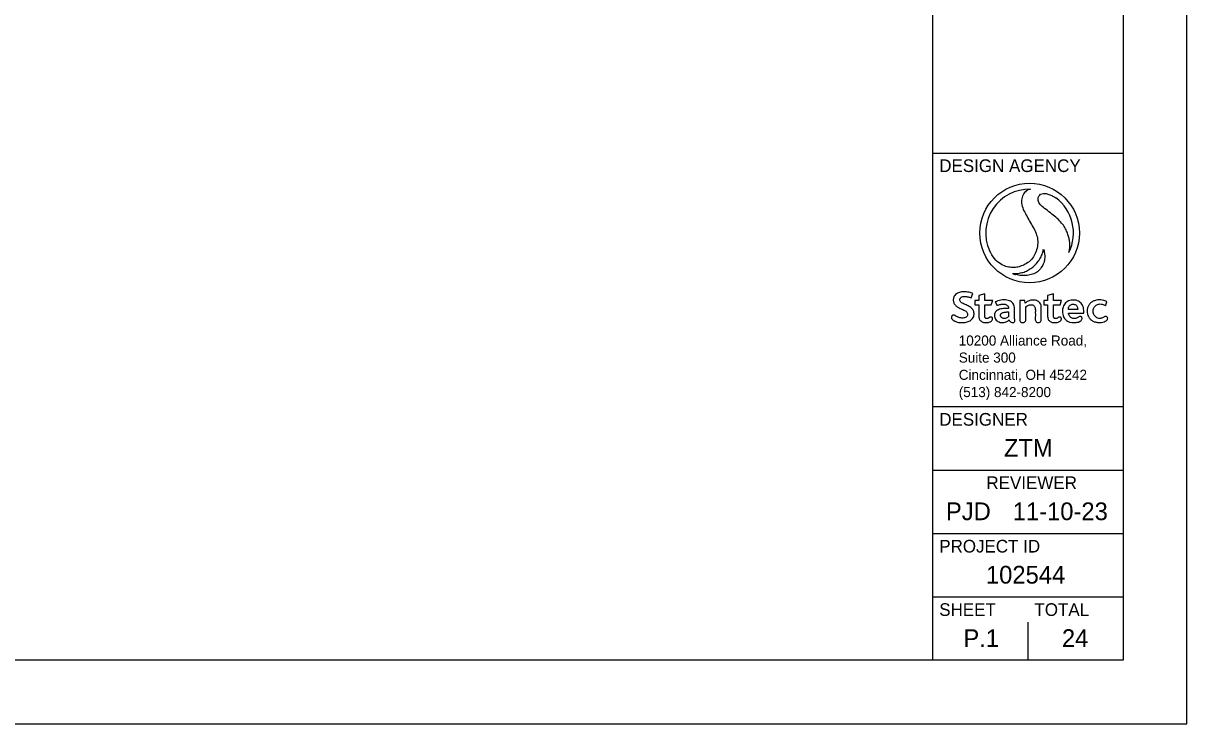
# Model space of a CAD drawing. Extents: x 0 to 45, y -99 to 22.
# Drawn here: x 24.83 to 34, y 0 to 5.52 of the extents above; entities that cross this region are included whole.
import ezdxf

# ---------------------------------------------------------------- set-up
doc = ezdxf.new("R2010")
doc.units = 0
for name, color, linetype in [('SH_Border', 7, 'Continuous'), ('SH_Cut_Line', 7, 'Continuous'), ('SH_Data', 7, 'Continuous'), ('SH_Text', 7, 'Continuous')]:
    doc.layers.add(name, color=color, linetype=linetype)

msp = doc.modelspace()

# ---------------------------------------------------------------- linework, layer by layer
at = {"layer": 'SH_Border'}
for p, q in [((32, 0.5), (32, 21.5)), ((32, 4.5), (33.5, 4.5)), ((32, 2.5), (33.5, 2.5)), ((32, 2), (33.5, 2)), ((32, 1.5), (33.5, 1.5)), ((32, 1), (33.5, 1))]:
    msp.add_line(p, q, dxfattribs=at)
msp.add_lwpolyline([(1.5, 21.5), (33.5, 21.5), (33.5, 0.5), (1.5, 0.5)], close=True, dxfattribs=at)
at = {"layer": 'SH_Cut_Line'}
for p, q in [((32.75, 3.5), (32.75, 3.5)), ((32.75, 0.5), (32.75, 0.8)), ((32.375, 0.675), (32.375, 0.675))]:
    msp.add_line(p, q, dxfattribs=at)
at = {"layer": 'SH_Data'}
msp.add_lwpolyline([(0, 0), (34, 0), (34, 22), (0, 22)], close=True, dxfattribs=at)
at = {"layer": 'SH_Text'}
for p, q in [((32.3019, 3.3581), (32.3138, 3.392)), ((32.3616, 3.3362), (32.3311, 3.3362)), ((32.3311, 3.3362), (32.3311, 3.3028)), ((32.3311, 3.3028), (32.3619, 3.3028)), ((32.4095, 3.3895), (32.3616, 3.3761)), ((32.3616, 3.3761), (32.3616, 3.3362)), ((32.4085, 3.2186), (32.4092, 3.3028)), ((32.4092, 3.3028), (32.4599, 3.3028)), ((32.4095, 3.3362), (32.4095, 3.3895)), ((32.4715, 3.3362), (32.4095, 3.3362)), ((32.4599, 3.3028), (32.4715, 3.3362)), ((32.4915, 3.3253), (32.5061, 3.297)), ((32.7248, 3.3368), (32.6845, 3.3368)), ((32.6845, 3.3368), (32.6845, 3.1839)), ((32.7275, 3.3166), (32.7248, 3.3368)), ((32.9034, 3.3362), (32.873, 3.3362)), ((32.873, 3.3362), (32.873, 3.3028)), ((32.873, 3.3028), (32.9038, 3.3028)), ((32.9514, 3.3895), (32.9034, 3.3761)), ((32.9034, 3.3761), (32.9034, 3.3362)), ((32.9504, 3.2186), (32.9511, 3.3028)), ((32.9511, 3.3028), (33.0018, 3.3028)), ((32.9514, 3.3362), (32.9514, 3.3895)), ((33.0134, 3.3362), (32.9514, 3.3362)), ((33.0018, 3.3028), (33.0134, 3.3362)), ((33.3594, 3.296), (33.37, 3.3273)), ((32.5963, 3.2468), (32.5963, 3.209)), ((32.7314, 3.1839), (32.7314, 3.2849)), ((33.1411, 3.2652), (33.0679, 3.2652)), ((33.0679, 3.2359), (33.1896, 3.2359))]:
    msp.add_line(p, q, dxfattribs=at)
for points in [[(32.7692, 4.2147), (32.7692, 4.2147)], [(32.9678, 4.1468), (32.9678, 4.1467)]]:
    msp.add_lwpolyline(points, dxfattribs=at)
msp.add_circle((32.7617, 3.869), 0.3923, dxfattribs=at)
for start, end in [(88.76659, 203.68447), (88.76015, 88.76659), (333.78149, 53.43262), (247.1184, 251.45797)]:
    msp.add_arc((32.7617, 3.869), 0.3458, start, end, dxfattribs=at)
for points, degree in [([(32.7692, 4.2147), (32.7608, 4.213), (32.7412, 4.2088), (32.7155, 4.1826), (32.6965, 4.1396), (32.6989, 4.0913), (32.716, 4.0446), (32.7418, 3.9993), (32.7685, 3.9492), (32.7981, 3.9019), (32.8186, 3.854), (32.8284, 3.8018), (32.822, 3.7495), (32.8068, 3.7015), (32.7773, 3.6579), (32.7385, 3.627), (32.6979, 3.6088), (32.6613, 3.5974), (32.6204, 3.5975), (32.5748, 3.6039), (32.5299, 3.6244), (32.4821, 3.6649), (32.4591, 3.7047), (32.445, 3.7301)], 3), ([(32.7692, 4.2147), (32.7692, 4.2147), (32.7692, 4.2147), (32.7692, 4.2147)], 2), ([(33.072, 3.7162), (33.075, 3.7283), (33.0801, 3.7511), (33.0792, 3.7877), (33.0757, 3.8197), (33.0662, 3.8496), (33.0551, 3.884), (33.0356, 3.9215), (33.0077, 3.9567), (32.9713, 3.9939), (32.9258, 4.0269), (32.879, 4.0652), (32.8415, 4.0934), (32.8282, 4.1266), (32.8282, 4.1518), (32.8405, 4.1689), (32.8572, 4.1807), (32.8793, 4.1827), (32.9054, 4.1777), (32.9356, 4.1649), (32.9565, 4.1532), (32.9678, 4.1468)], 3), ([(32.6273, 3.5504), (32.6358, 3.5495), (32.6558, 3.5475), (32.6901, 3.5542), (32.7283, 3.5632), (32.7628, 3.5832), (32.7945, 3.6055), (32.8243, 3.6375), (32.8491, 3.6731), (32.8647, 3.7101), (32.8694, 3.732), (32.8717, 3.7424)], 3), ([(32.8717, 3.7424), (32.8743, 3.7336), (32.8807, 3.7111), (32.8823, 3.6736), (32.8759, 3.6329), (32.8549, 3.5959), (32.8266, 3.5618), (32.7856, 3.5431), (32.742, 3.5333), (32.6972, 3.5325), (32.6664, 3.5383), (32.6518, 3.5411)], 3), ([(32.3138, 3.392), (32.3117, 3.393), (32.3022, 3.3975), (32.2841, 3.4023), (32.262, 3.405), (32.2419, 3.406), (32.2251, 3.4044), (32.209, 3.4011), (32.1935, 3.3949), (32.1785, 3.3847), (32.1678, 3.3709), (32.1617, 3.3571), (32.1604, 3.3441), (32.1609, 3.3323), (32.1635, 3.3209), (32.1683, 3.3115), (32.1741, 3.303), (32.1814, 3.2953), (32.1901, 3.2883), (32.2009, 3.2817), (32.2142, 3.2749), (32.229, 3.2681), (32.2441, 3.2617), (32.2565, 3.2553), (32.2656, 3.2475), (32.2719, 3.2403), (32.274, 3.2313), (32.2738, 3.2229), (32.2703, 3.2135), (32.2625, 3.2058), (32.2503, 3.2004), (32.2356, 3.1983), (32.2195, 3.199), (32.2051, 3.202), (32.1936, 3.2078), (32.1842, 3.2116), (32.1779, 3.2175), (32.1719, 3.2198), (32.1664, 3.2222), (32.1605, 3.2218), (32.1546, 3.2199), (32.1495, 3.2156), (32.1462, 3.2094), (32.146, 3.2026), (32.147, 3.1959), (32.1523, 3.1887), (32.1625, 3.1786), (32.1806, 3.1697), (32.2029, 3.1637), (32.2255, 3.1625), (32.2451, 3.1631), (32.2621, 3.1653), (32.277, 3.1698), (32.2926, 3.1769), (32.3076, 3.1886), (32.3192, 3.2032), (32.324, 3.2204), (32.3247, 3.2359), (32.3228, 3.25), (32.3173, 3.2613), (32.3106, 3.2725), (32.2989, 3.2821), (32.2857, 3.2909), (32.2711, 3.298), (32.2554, 3.3054), (32.239, 3.3124), (32.225, 3.3197), (32.2156, 3.3282), (32.2117, 3.3365), (32.2109, 3.3452), (32.2135, 3.3531), (32.2188, 3.36), (32.2263, 3.3649), (32.2361, 3.3685), (32.2479, 3.3694), (32.2596, 3.3689), (32.2711, 3.3671), (32.2823, 3.3647), (32.2928, 3.3615), (32.2991, 3.3591), (32.3019, 3.3581)], 3), ([(32.3619, 3.3028), (32.3617, 3.273), (32.3616, 3.2416), (32.362, 3.2065), (32.3635, 3.1981), (32.3668, 3.1866), (32.3733, 3.1789), (32.3799, 3.1728), (32.3869, 3.1681), (32.3981, 3.1642), (32.4134, 3.1625), (32.4292, 3.1632), (32.445, 3.1654), (32.4571, 3.1715), (32.4659, 3.1787), (32.4701, 3.1869), (32.4705, 3.1941), (32.4692, 3.2001), (32.466, 3.2037), (32.4622, 3.206), (32.4577, 3.2068), (32.453, 3.2069), (32.4482, 3.2057), (32.4439, 3.2022), (32.4391, 3.1986), (32.4331, 3.196), (32.4268, 3.194), (32.4203, 3.1947), (32.4146, 3.1978), (32.4103, 3.2022), (32.4084, 3.2097), (32.4085, 3.2151), (32.4085, 3.2186)], 3), ([(32.6009, 3.1853), (32.6011, 3.1837), (32.6014, 3.1797), (32.6054, 3.1738), (32.611, 3.1673), (32.6212, 3.1625), (32.632, 3.1629), (32.642, 3.1651), (32.6459, 3.173), (32.6461, 3.181), (32.6438, 3.1916), (32.6413, 3.221), (32.6432, 3.252), (32.6427, 3.2855), (32.6388, 3.3017), (32.6297, 3.3163), (32.6198, 3.3275), (32.6036, 3.3357), (32.5836, 3.3409), (32.5598, 3.3424), (32.5358, 3.3401), (32.5126, 3.3347), (32.4984, 3.3283), (32.4915, 3.3253)], 3), ([(32.5061, 3.297), (32.5083, 3.2982), (32.515, 3.3017), (32.5259, 3.3051), (32.5389, 3.3084), (32.5514, 3.3093), (32.5643, 3.3088), (32.5759, 3.3052), (32.586, 3.2994), (32.5931, 3.2908), (32.5962, 3.2822), (32.5962, 3.2769), (32.5962, 3.2751)], 3), ([(32.7314, 3.2849), (32.7322, 3.2856), (32.7355, 3.2886), (32.7434, 3.2934), (32.7535, 3.3001), (32.7665, 3.304), (32.7796, 3.3039), (32.7923, 3.2998), (32.801, 3.2908), (32.8057, 3.28), (32.8081, 3.2655), (32.8065, 3.2437), (32.8077, 3.216), (32.8062, 3.1931), (32.8072, 3.1771), (32.8127, 3.1686), (32.8222, 3.1625), (32.8333, 3.1628), (32.8439, 3.1653), (32.8525, 3.1718), (32.8551, 3.1844), (32.8532, 3.2067), (32.8544, 3.234), (32.8538, 3.2641), (32.8549, 3.2832), (32.8523, 3.2998), (32.8471, 3.3115), (32.8389, 3.3234), (32.8255, 3.3328), (32.8088, 3.3407), (32.7896, 3.3412), (32.7724, 3.3402), (32.7569, 3.3351), (32.7432, 3.3287), (32.734, 3.3215), (32.7291, 3.3178), (32.7275, 3.3166)], 3), ([(32.9038, 3.3028), (32.9036, 3.273), (32.9035, 3.2416), (32.9038, 3.2065), (32.9054, 3.1981), (32.9087, 3.1866), (32.9152, 3.1789), (32.9218, 3.1728), (32.9288, 3.1681), (32.9399, 3.1642), (32.9553, 3.1625), (32.9711, 3.1632), (32.9869, 3.1654), (32.999, 3.1715), (33.0078, 3.1787), (33.0119, 3.1869), (33.0124, 3.1941), (33.0111, 3.2001), (33.0079, 3.2037), (33.0041, 3.206), (32.9996, 3.2068), (32.9949, 3.2069), (32.9901, 3.2057), (32.9858, 3.2022), (32.9809, 3.1986), (32.975, 3.196), (32.9687, 3.194), (32.9622, 3.1947), (32.9565, 3.1978), (32.9521, 3.2022), (32.9503, 3.2097), (32.9504, 3.2151), (32.9504, 3.2186)], 3), ([(33.1896, 3.2359), (33.1898, 3.2405), (33.1902, 3.2522), (33.1881, 3.2709), (33.1834, 3.2919), (33.1733, 3.3082), (33.1619, 3.3223), (33.1474, 3.3322), (33.129, 3.3395), (33.1084, 3.3408), (33.0881, 3.3404), (33.0689, 3.3344), (33.0525, 3.3249), (33.0381, 3.3113), (33.0284, 3.2948), (33.0229, 3.2767), (33.0208, 3.2582), (33.0206, 3.2383), (33.025, 3.2198), (33.0323, 3.2018), (33.0434, 3.1865), (33.0603, 3.1743), (33.0814, 3.1638), (33.1059, 3.1625), (33.1282, 3.1628), (33.1472, 3.1668), (33.1621, 3.1741), (33.173, 3.1835), (33.1769, 3.1938), (33.1751, 3.2021), (33.1711, 3.2087), (33.1645, 3.2105), (33.1581, 3.2114), (33.1506, 3.209), (33.1417, 3.2035), (33.1316, 3.1974), (33.1192, 3.1946), (33.1077, 3.1943), (33.0964, 3.1972), (33.087, 3.2037), (33.0778, 3.2113), (33.0723, 3.2214), (33.0689, 3.2297), (33.0682, 3.2343), (33.0679, 3.2359)], 3), ([(33.0679, 3.2652), (33.0679, 3.2667), (33.0679, 3.2705), (33.0684, 3.2776), (33.0708, 3.2868), (33.0765, 3.2964), (33.0853, 3.3042), (33.0974, 3.3085), (33.1104, 3.3088), (33.1225, 3.3051), (33.1328, 3.2985), (33.1379, 3.2873), (33.1405, 3.2761), (33.1409, 3.2685), (33.1411, 3.2652)], 3), ([(33.37, 3.3273), (33.366, 3.3296), (33.356, 3.3352), (33.3365, 3.3403), (33.3123, 3.3428), (33.2865, 3.3398), (33.2619, 3.3318), (33.2416, 3.3182), (33.2268, 3.2997), (33.2177, 3.2784), (33.2145, 3.2545), (33.2164, 3.2304), (33.2246, 3.2088), (33.2368, 3.1922), (33.2538, 3.1777), (33.277, 3.1669), (33.3043, 3.1625), (33.3292, 3.1642), (33.3499, 3.1696), (33.3663, 3.1772), (33.3769, 3.1874), (33.3775, 3.1972), (33.3766, 3.2045), (33.3717, 3.2089), (33.3666, 3.2119), (33.3611, 3.2123), (33.3536, 3.2111), (33.3469, 3.2053), (33.3372, 3.2012), (33.3275, 3.1966), (33.3136, 3.1956), (33.2991, 3.1969), (33.2851, 3.2044), (33.2747, 3.215), (33.2663, 3.2276), (33.2638, 3.2425), (33.2616, 3.2573), (33.2658, 3.2719), (33.2714, 3.2852), (33.2797, 3.2959), (33.2909, 3.3038), (33.3036, 3.3088), (33.3186, 3.31), (33.3335, 3.3086), (33.3479, 3.3041), (33.3557, 3.2986), (33.3594, 3.296)], 3), ([(32.5962, 3.2751), (32.5931, 3.275), (32.583, 3.2748), (32.5656, 3.274), (32.545, 3.2729), (32.5256, 3.2686), (32.5078, 3.2613), (32.4922, 3.2478), (32.4849, 3.2289), (32.4859, 3.2111), (32.4888, 3.1957), (32.4981, 3.1828), (32.5116, 3.171), (32.5309, 3.1637), (32.551, 3.1635), (32.5695, 3.1658), (32.5836, 3.1708), (32.5941, 3.178), (32.5985, 3.1827), (32.6009, 3.1853)], 3), ([(32.5963, 3.209), (32.5951, 3.2081), (32.5907, 3.2046), (32.5825, 3.2002), (32.5712, 3.1956), (32.5591, 3.1948), (32.5486, 3.1976), (32.5413, 3.2023), (32.5365, 3.2079), (32.5334, 3.2146), (32.5329, 3.2218), (32.5343, 3.229), (32.5386, 3.2358), (32.5459, 3.2402), (32.5547, 3.2441), (32.5663, 3.2457), (32.5782, 3.2463), (32.5886, 3.247), (32.5941, 3.2469), (32.5963, 3.2468)], 3), ([(32.6845, 3.1839), (32.6849, 3.1819), (32.6859, 3.1774), (32.6893, 3.1696), (32.6979, 3.1631), (32.7098, 3.163), (32.7218, 3.1639), (32.7289, 3.1717), (32.7315, 3.1786), (32.7315, 3.1823), (32.7314, 3.1839)], 3)]:
    msp.add_open_spline(points, degree=degree, dxfattribs=at)

# ---------------------------------------------------------------- texts
at = {"layer": 'SH_Cut_Line'}
for s, height, p in [('DESIGN AGENCY', 0.1, (32.05, 4.35)), ('DESIGNER', 0.1, (32.05, 2.35)), ('ZTM', 0.14, (32.5595, 2.105)), ('REVIEWER', 0.1, (32.4218, 1.85)), ('PJD', 0.14, (32.1026, 1.605)), ('11-10-23', 0.14, (32.6289, 1.605)), ('PROJECT ID', 0.1, (32.05, 1.35)), ('102544', 0.14, (32.4179, 1.105)), ('SHEET', 0.1, (32.05, 0.85)), ('TOTAL', 0.1, (32.8, 0.85)), ('P.1', 0.14, (32.2403, 0.605)), ('24', 0.14, (33.0164, 0.605))]:
    msp.add_text(s, height=height, dxfattribs=at).set_placement(p)
at = {"layer": 'SH_Text'}
for s, height, p in [('10200 Alliance Road,', 0.079484, (32.2038, 2.9817)), ('Suite 300', 0.07948, (32.2038, 2.8473)), ('Cincinnati, OH 45242', 0.079484, (32.2038, 2.7113)), ('(513) 842-8200', 0.079484, (32.2038, 2.5754))]:
    msp.add_text(s, height=height, rotation=360, dxfattribs=at).set_placement(p)

doc.saveas('drawing.dxf')
